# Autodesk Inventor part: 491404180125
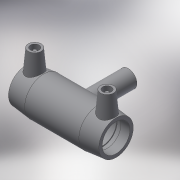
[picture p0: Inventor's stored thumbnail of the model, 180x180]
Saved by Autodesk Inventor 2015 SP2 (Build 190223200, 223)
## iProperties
Created: 2017-06
Part Number: 491404180125
Material: Generic
Description: PLASSON REDUCING TEE 180x125x180
Document SubType Name: Modeling
Designer: KIM
Mass: 57.3761 g
Surface Area: 241.06 cm^2
Volume: 57.3761 cm^3
Density: 1 g/cm^3
Appearance: Default
Author: KIM
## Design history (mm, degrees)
derived "491404.ipt"
feature "Solid1::491404.ipt"
tag "TaggingFeature1"
body "Solid1"
other parameters: "d0" = 422, "d2" = 245, "d3" = 106, "d4" = 84.4, "d5" = 220.5, "d6" = 171, "d8" = 168 deg, "d10" = 42.4, "d11" = 14.13333, "d13" = 422, "d14" = 17.6296, "d17" = 162, "d19" = 3.52592, "d20" = 168 deg, "d22" = 227.85, "d23" = 245, "d25" = 135 deg, "d26" = 295.4, "d29" = 116, "d30" = 15, "d31" = 168.8, "d34" = 5 deg, "d35" = 15, "d39" = 5 deg, "d41" = 4, "d42" = 14, "d43" = 0, "d45" = 4, "d46" = 6, "d47" = 0, "d48" = -225, "d49" = 125, "d51" = 0, "d54" = 0, "d55" = 220.5, "d56" = 245, "d57" = 147.7, "d58" = 135 deg, "d59" = 106, "d60" = 106, "d61" = 135 deg, "d62" = 225, "d72" = 192.01, "d73" = 96.005, "d74" = -225, "d75" = 131.25, "d77" = 0, "d80" = 0, "d81" = 125, "d82" = 102.5, "d83" = 0, "d84" = 3, "d85" = 0, "d86" = 35.33333, "d87" = 223.293, "d88" = 14.13333, "d89" = 3, "d90" = 0, "L_" = 422, "L_1" = 106, "D_" = 245, "A_" = 116, "d_2" = 12, "H_" = 225, "d_1" = 125
